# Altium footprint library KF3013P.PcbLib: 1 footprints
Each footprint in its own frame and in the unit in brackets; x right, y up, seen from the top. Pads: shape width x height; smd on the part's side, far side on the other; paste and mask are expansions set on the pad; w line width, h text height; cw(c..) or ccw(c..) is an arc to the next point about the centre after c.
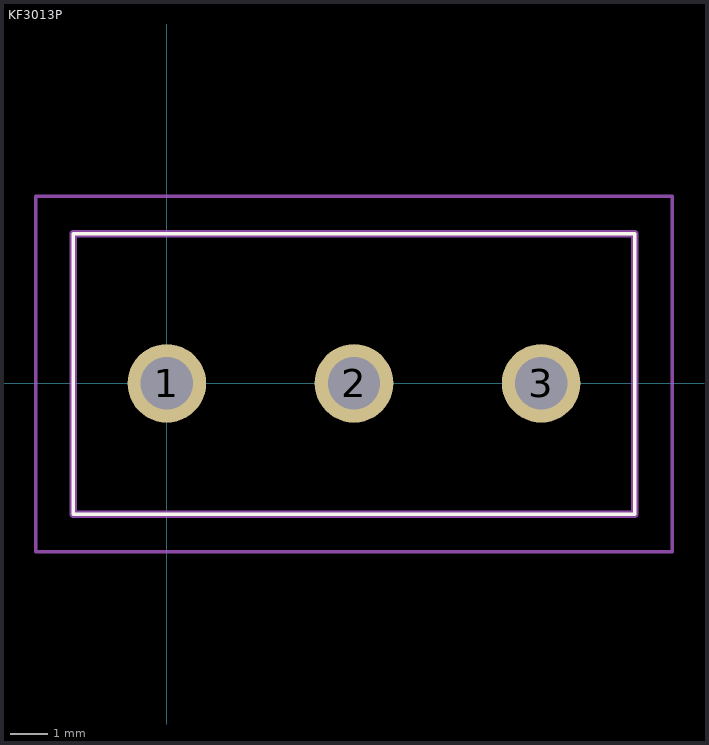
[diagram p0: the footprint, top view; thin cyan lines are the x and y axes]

## KF3013P [mm]
pads (3):
  round 2.1 hole 1.4: 1(0,0) 2(5,0) 3(10,0)
Top Overlay:
  lines w0.1: -2.5,-3.5 12.5,-3.5 12.5,4 -2.5,4 -2.5,-3.5
Mechanical 15:
  lines w0.2: -2.5,-3.5 12.5,-3.5 12.5,4 -2.5,4 -2.5,-3.5
Mechanical 20:
  lines w0.1: -3.5,-4.5 13.5,-4.5 13.5,5 -3.5,5 -3.5,-4.5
